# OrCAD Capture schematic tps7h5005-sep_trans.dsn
size Custom; title: TPS7H5005-SEP Radiation Tolerant 2-MHz; rev: *; note: Datasheet: SLVSGG1    EVM User Guide: SLVUCD8; note: Current Mode PWM Controller
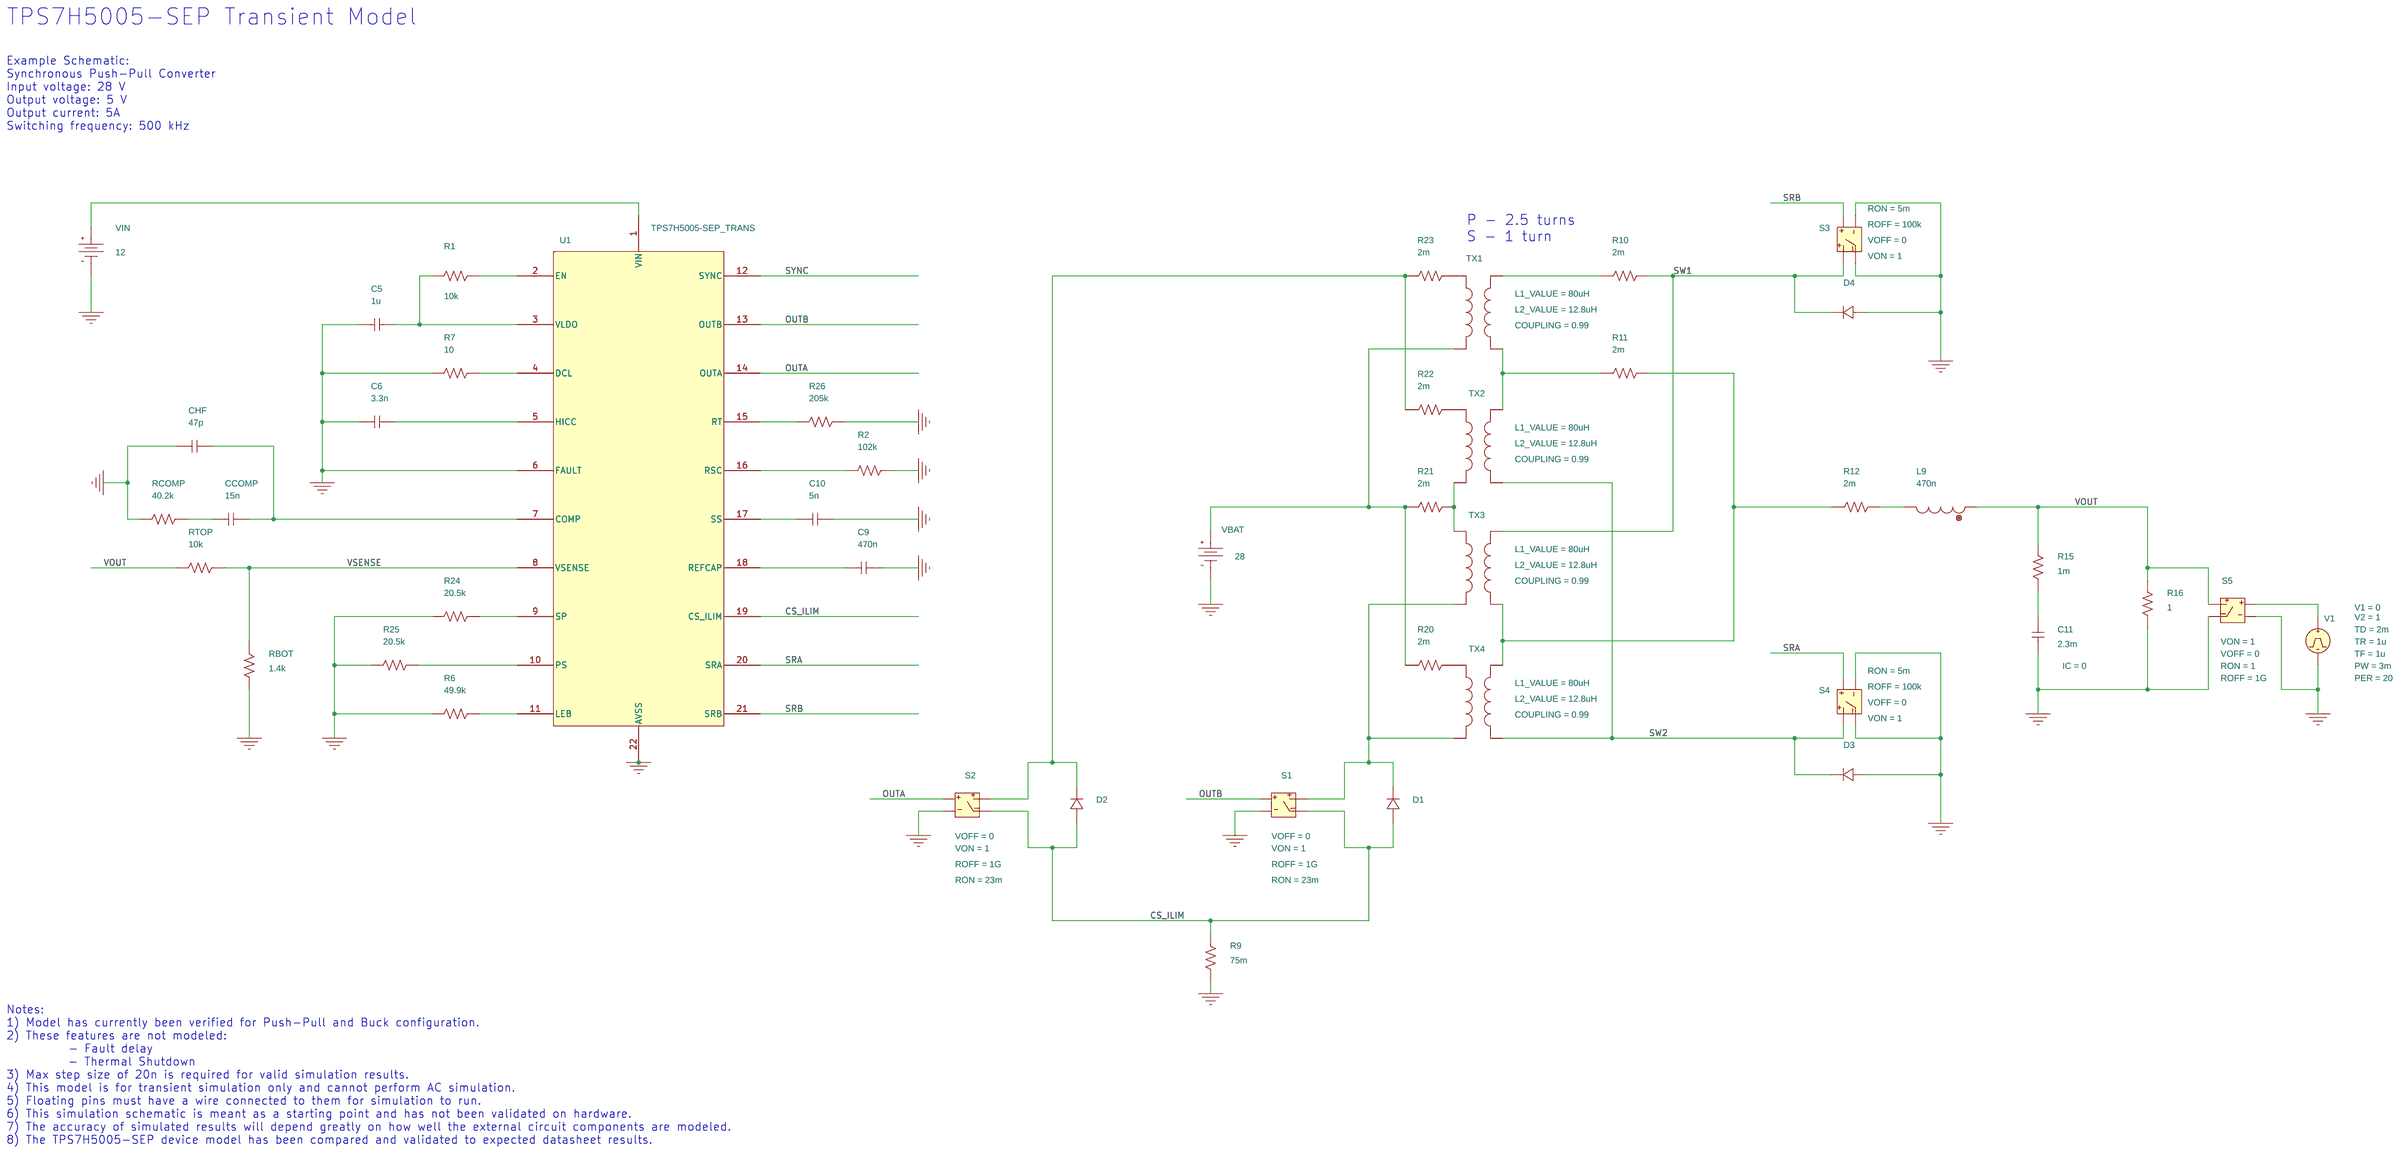
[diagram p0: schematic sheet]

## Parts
C5  1u  [cap196]
C6  3.3n  [cap196]
C9  470n  [cap196]
C10  5n  [cap196]
C11  2.3m  [cap196]
CCOMP  15n  [cap196]
CHF  47p  [cap196]
D1  Dbreak
D2  Dbreak
D3  Dbreak
D4  Dbreak
L9  470n  [DISC350x175LS200x100034]
R1  10k  [AXRC05]
R2  102k  [AXRC05]
R6  49.9k  [AXRC05]
R7  10  [AXRC05]
R9  75m  [AXRC05]
R10  2m  [AXRC05]
R11  2m  [AXRC05]
R12  2m  [AXRC05]
R15  1m  [AXRC05]
R16  1  [AXRC05]
R20  2m  [AXRC05]
R21  2m  [AXRC05]
R22  2m  [AXRC05]
R23  2m  [AXRC05]
R24  20.5k  [AXRC05]
R25  20.5k  [AXRC05]
R26  205k  [AXRC05]
RBOT  1.4k  [AXRC05]
RCOMP  40.2k  [AXRC05]
RTOP  10k  [AXRC05]
S1  S
S2  S
S3  S
S4  S
S5  S
TX1  XFRM_LINEAR
TX2  XFRM_LINEAR
TX3  XFRM_LINEAR
TX4  XFRM_LINEAR
U1  TPS7H5005-SEP_TRANS
V1  VPULSE
VBAT  VDC
VIN  VDC

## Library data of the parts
C5 C6 C9 C10 CCOMP CHF = C
C11 = C: IC: 0
D1-D4 = Dbreak
L9 = L
R1 R2 R6 R7 R9-R12 R15 R16 R20-R26 RBOT RCOMP RTOP = R
S1 S2 = S: ROFF: 1G; RON: 23m; VOFF: 0; VON: 1
S3 S4 = S: ROFF: 100k; RON: 5m; VOFF: 0; VON: 1
S5 = S: ROFF: 1G; RON: 1; VOFF: 0; VON: 1
TX1-TX4 = XFRM_LINEAR: COUPLING: 0.99; L1_VALUE: 80uH; L2_VALUE: 12.8uH
U1 = TPS7H5005-SEP_TRANS_0: PSpiceTemplate: X^@REFDES  %VIN %EN %VLDO %DCL %HICC %FAULT %COMP %VSENSE %SP %PS %LEB %SYNC %OUTB %OUTA %RT %RSC %SS %REFCAP %CS_ILIM %SRA %SRB %AVSS @MODEL
V1 = VPULSE: PER: 20; PW: 3m; TD: 2m; TF: 1u; TR: 1u; V1: 0; V2: 1
VBAT = VDC: DC: 28
VIN = VDC: DC: 12

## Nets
0: C5.2 C6.2 C9.1 C10.1 C11.1 CHF.2 D3.0(1) D4.0(1) R2.1 R6.2 R7.2 R9.2 R16.1 R24.2 R25.2 R26.1 RBOT.2 RCOMP.2 S1.1(2) S2.1(2) S3.1(2) S3.3(4) S4.1(2) S4.3(4) S5.1(2) S5.3(4) U1.6(FAULT) U1.22(AVSS) V1.2(-) VBAT.1(-) VIN.1(-)
CS_ILIM: D1.0(1) D2.0(1) R9.1 S1.3(4) S2.3(4) U1.19(CS_ILIM)
OUTA: S2.0(1) U1.14(OUTA)
OUTB: S1.0(1) U1.13(OUTB)
SRA: S4.0(1) U1.20(SRA)
SRB: S3.0(1) U1.21(SRB)
SW1: D4.1(2) R10.2 S3.2(3) TX3.3
SW2: D3.1(2) S4.2(3) TX2.4 TX4.4
SYNC: U1.12(SYNC)
VOUT: L9.1 R15.2 R16.2 RTOP.2 S5.2(3)
VSENSE: RBOT.1 RTOP.1 U1.8(VSENSE)
N74628: U1.1(VIN) VIN.0(+)
N74694: D2.1(2) R22.1 R23.1 S2.2(3)
N74740: R10.1 TX1.3
N74872: C5.1 R1.2 U1.3(VLDO)
N74880: R1.1 U1.2(EN)
N74898: R20.1 R21.1 TX1.2 VBAT.0(+)
N74908: R11.1 TX1.4 TX2.3
N74980: R11.2 R12.1 TX3.4 TX4.3
N75098: R7.1 U1.4(DCL)
N75166: C6.1 U1.5(HICC)
N75172: R26.2 U1.15(RT)
N75184: R21.2 TX2.2 TX3.1
N75272: CCOMP.1 CHF.1 U1.7(COMP)
N75314: L9.2 R12.2
N75410: R2.2 U1.16(RSC)
N75596: CCOMP.2 RCOMP.1
N75612: C10.2 U1.17(SS)
N75630: C11.2 R15.1
N75704: D1.1(2) S1.2(3) TX3.2 TX4.2
N75720: S5.0(1) V1.1(+)
N75812: C9.2 U1.18(REFCAP)
N76020: R24.1 U1.9(SP)
N76162: R25.1 U1.10(PS)
N76312: R6.1 U1.11(LEB)
N16778124: R22.2 TX2.1
N16778125: R20.2 TX4.1
N16778126: R23.2 TX1.1

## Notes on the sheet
- TPS7H5005-SEP Transient Model
- Example Schematic:
  Synchronous Push-Pull Converter
  Input voltage: 28 V
  Output voltage: 5 V
  Output current: 5A
  Switching frequency: 500 kHz
- P - 2.5 turns
  S - 1 turn
- Notes:
  1) Model has currently been verified for Push-Pull and Buck configuration.
  2) These features are not modeled:
            - Fault delay
            - Thermal Shutdown
  3) Max step size of 20n is required for valid simulation results.
  4) This model is for transient simulation only and cannot perform AC simulation.
  5) Floating pins must have a wire connected to them for simulation to run.
  6) This simulation schematic is meant as a starting point and has not been validated on hardware.
  7) The accuracy of simulated results will depend greatly on how well the external circuit components are modeled.
  8) The TPS7H5005-SEP device model has been compared and validated to expected datasheet results.
